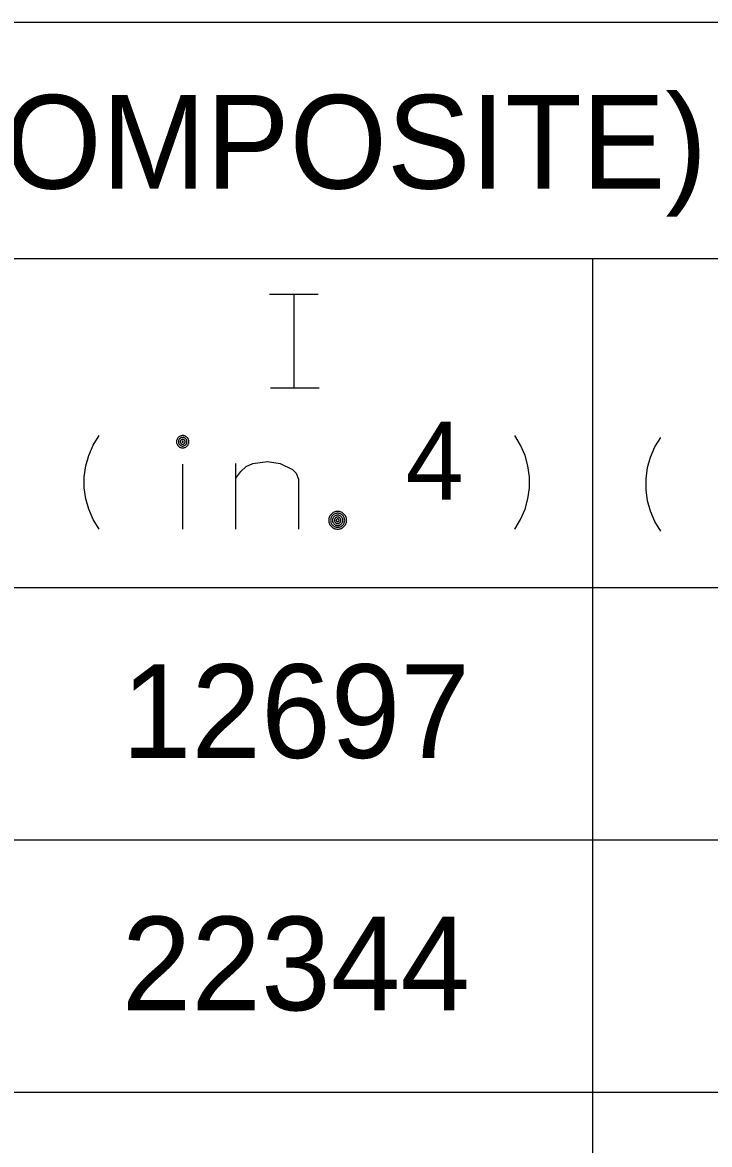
# Model space of a CAD drawing. Extents: x 635698 to 639877, y 296617 to 300175.
# Drawn here: x 639271.54 to 639293.54, y 299928.62 to 299964.57 of the extents above; entities that cross this region are included whole.
import ezdxf

# ---------------------------------------------------------------- set-up
doc = ezdxf.new("R2010")
doc.units = 0
doc.layers.add('1', color=7, linetype='Continuous')
doc.layers.add('3', color=7, linetype='Continuous')

msp = doc.modelspace()

# ---------------------------------------------------------------- linework, layer by layer
at = {"layer": '1'}
for p, q in [((639324.489, 299964.569), (639056.863, 299964.569)), ((639324.443, 299956.999), (639199.996, 299956.999)), ((639289.794, 299956.999), (639289.794, 299833.29)), ((639324.474, 299946.456), (639199.998, 299946.456)), ((639324.489, 299938.372), (639199.977, 299938.372)), ((639324.443, 299938.372), (639199.998, 299938.372)), ((639324.458, 299930.287), (639199.956, 299930.287)), ((639324.489, 299930.287), (639199.977, 299930.287))]:
    msp.add_line(p, q, dxfattribs=at)
at = {"layer": '3'}
for p, q in [((639279.457, 299955.864), (639281.01, 299955.864)), ((639279.486, 299952.859), (639281.039, 299952.859))]:
    msp.add_line(p, q, dxfattribs=at)
for points in [[(639279.885, 299955.862), (639280.593, 299955.862)], [(639280.239, 299952.862), (639280.239, 299955.862)], [(639279.885, 299952.862), (639280.593, 299952.862)], [(639273.995, 299948.335), (639273.806, 299948.642), (639273.664, 299948.973), (639273.57, 299949.303), (639273.522, 299949.658), (639273.522, 299950.012), (639273.57, 299950.367), (639273.664, 299950.697), (639273.806, 299951.028), (639273.995, 299951.335)], [(639276.871, 299951.137), (639276.87, 299951.157), (639276.867, 299951.178), (639276.861, 299951.198), (639276.854, 299951.217), (639276.844, 299951.236), (639276.833, 299951.253), (639276.82, 299951.269), (639276.805, 299951.284), (639276.789, 299951.297), (639276.772, 299951.308), (639276.754, 299951.318), (639276.734, 299951.325), (639276.714, 299951.33), (639276.694, 299951.334), (639276.673, 299951.335), (639276.652, 299951.334), (639276.632, 299951.33), (639276.612, 299951.325), (639276.592, 299951.318), (639276.574, 299951.308), (639276.557, 299951.297), (639276.54, 299951.284), (639276.526, 299951.269), (639276.513, 299951.253), (639276.502, 299951.236), (639276.492, 299951.217), (639276.485, 299951.198), (639276.479, 299951.178), (639276.476, 299951.157), (639276.475, 299951.137), (639276.476, 299951.116), (639276.479, 299951.095), (639276.485, 299951.076), (639276.492, 299951.056), (639276.502, 299951.038), (639276.513, 299951.02), (639276.526, 299951.004), (639276.54, 299950.99), (639276.557, 299950.976), (639276.574, 299950.965), (639276.592, 299950.956), (639276.612, 299950.949), (639276.632, 299950.943), (639276.652, 299950.94), (639276.673, 299950.939), (639276.694, 299950.94), (639276.714, 299950.943), (639276.734, 299950.949), (639276.754, 299950.956), (639276.772, 299950.965), (639276.789, 299950.977), (639276.805, 299950.99), (639276.82, 299951.004), (639276.833, 299951.02), (639276.844, 299951.038), (639276.854, 299951.056), (639276.861, 299951.076), (639276.867, 299951.095), (639276.87, 299951.116), (639276.871, 299951.137)], [(639287.304, 299948.335), (639287.493, 299948.642), (639287.634, 299948.973), (639287.729, 299949.303), (639287.776, 299949.658), (639287.776, 299950.012), (639287.729, 299950.367), (639287.634, 299950.697), (639287.493, 299951.028), (639287.304, 299951.335)], [(639276.811, 299951.137), (639276.81, 299951.151), (639276.808, 299951.165), (639276.804, 299951.179), (639276.799, 299951.193), (639276.792, 299951.206), (639276.785, 299951.218), (639276.776, 299951.229), (639276.765, 299951.239), (639276.754, 299951.248), (639276.742, 299951.256), (639276.729, 299951.263), (639276.715, 299951.268), (639276.702, 299951.272), (639276.687, 299951.274), (639276.673, 299951.275), (639276.658, 299951.274), (639276.644, 299951.272), (639276.63, 299951.268), (639276.617, 299951.263), (639276.604, 299951.256), (639276.592, 299951.248), (639276.581, 299951.239), (639276.57, 299951.229), (639276.561, 299951.218), (639276.553, 299951.206), (639276.547, 299951.193), (639276.542, 299951.179), (639276.538, 299951.165), (639276.536, 299951.151), (639276.535, 299951.137), (639276.536, 299951.122), (639276.538, 299951.108), (639276.542, 299951.094), (639276.547, 299951.081), (639276.553, 299951.068), (639276.561, 299951.055), (639276.57, 299951.044), (639276.581, 299951.034), (639276.592, 299951.025), (639276.604, 299951.017), (639276.617, 299951.011), (639276.63, 299951.006), (639276.644, 299951.002), (639276.658, 299950.999), (639276.673, 299950.999), (639276.687, 299950.999), (639276.702, 299951.002), (639276.715, 299951.006), (639276.729, 299951.011), (639276.742, 299951.017), (639276.754, 299951.025), (639276.765, 299951.034), (639276.776, 299951.044), (639276.785, 299951.055), (639276.792, 299951.068), (639276.799, 299951.081), (639276.804, 299951.094), (639276.808, 299951.108), (639276.81, 299951.122), (639276.811, 299951.137)], [(639276.751, 299951.137), (639276.751, 299951.145), (639276.749, 299951.153), (639276.747, 299951.161), (639276.744, 299951.168), (639276.74, 299951.176), (639276.736, 299951.183), (639276.731, 299951.189), (639276.725, 299951.195), (639276.719, 299951.2), (639276.712, 299951.204), (639276.705, 299951.208), (639276.697, 299951.211), (639276.689, 299951.213), (639276.681, 299951.214), (639276.673, 299951.215), (639276.665, 299951.214), (639276.657, 299951.213), (639276.649, 299951.211), (639276.641, 299951.208), (639276.634, 299951.204), (639276.627, 299951.2), (639276.621, 299951.195), (639276.615, 299951.189), (639276.61, 299951.183), (639276.605, 299951.176), (639276.602, 299951.168), (639276.599, 299951.161), (639276.596, 299951.153), (639276.595, 299951.145), (639276.595, 299951.137), (639276.595, 299951.129), (639276.596, 299951.121), (639276.599, 299951.113), (639276.602, 299951.105), (639276.605, 299951.098), (639276.61, 299951.091), (639276.615, 299951.084), (639276.621, 299951.079), (639276.627, 299951.074), (639276.634, 299951.069), (639276.641, 299951.065), (639276.649, 299951.062), (639276.657, 299951.061), (639276.665, 299951.059), (639276.673, 299951.059), (639276.681, 299951.059), (639276.689, 299951.061), (639276.697, 299951.062), (639276.705, 299951.065), (639276.712, 299951.069), (639276.719, 299951.074), (639276.725, 299951.079), (639276.731, 299951.084), (639276.736, 299951.091), (639276.74, 299951.098), (639276.744, 299951.105), (639276.747, 299951.113), (639276.749, 299951.121), (639276.751, 299951.129), (639276.751, 299951.137)], [(639276.691, 299951.137), (639276.691, 299951.139), (639276.691, 299951.14), (639276.69, 299951.142), (639276.689, 299951.144), (639276.688, 299951.146), (639276.687, 299951.147), (639276.686, 299951.149), (639276.685, 299951.15), (639276.684, 299951.151), (639276.682, 299951.152), (639276.68, 299951.153), (639276.678, 299951.154), (639276.677, 299951.154), (639276.675, 299951.155), (639276.673, 299951.155), (639276.671, 299951.155), (639276.669, 299951.154), (639276.668, 299951.154), (639276.666, 299951.153), (639276.664, 299951.152), (639276.662, 299951.151), (639276.661, 299951.15), (639276.659, 299951.149), (639276.658, 299951.147), (639276.657, 299951.146), (639276.657, 299951.144), (639276.656, 299951.142), (639276.655, 299951.14), (639276.655, 299951.139), (639276.655, 299951.137), (639276.655, 299951.135), (639276.655, 299951.133), (639276.656, 299951.131), (639276.657, 299951.129), (639276.657, 299951.128), (639276.658, 299951.126), (639276.659, 299951.125), (639276.661, 299951.123), (639276.662, 299951.122), (639276.664, 299951.121), (639276.666, 299951.12), (639276.668, 299951.12), (639276.669, 299951.119), (639276.671, 299951.119), (639276.673, 299951.119), (639276.675, 299951.119), (639276.677, 299951.119), (639276.678, 299951.12), (639276.68, 299951.12), (639276.682, 299951.121), (639276.684, 299951.122), (639276.685, 299951.123), (639276.686, 299951.125), (639276.687, 299951.126), (639276.688, 299951.128), (639276.689, 299951.129), (639276.69, 299951.131), (639276.691, 299951.133), (639276.691, 299951.135), (639276.691, 299951.137)], [(639291.985, 299948.276), (639291.796, 299948.583), (639291.654, 299948.914), (639291.559, 299949.244), (639291.512, 299949.599), (639291.512, 299949.953), (639291.559, 299950.308), (639291.654, 299950.638), (639291.796, 299950.969), (639291.985, 299951.276)], [(639276.673, 299948.335), (639276.673, 299950.413)], [(639278.374, 299949.965), (639278.539, 299950.178), (639278.705, 299950.343), (639278.918, 299950.437), (639279.39, 299950.508), (639279.791, 299950.437), (639280.193, 299950.248), (639280.311, 299950.13), (639280.382, 299949.941), (639280.382, 299948.335)], [(639278.374, 299948.335), (639278.374, 299950.437)], [(639281.92, 299948.62), (639281.919, 299948.649), (639281.914, 299948.679), (639281.907, 299948.708), (639281.896, 299948.736), (639281.882, 299948.762), (639281.866, 299948.787), (639281.847, 299948.81), (639281.826, 299948.831), (639281.803, 299948.85), (639281.778, 299948.867), (639281.751, 299948.88), (639281.723, 299948.891), (639281.695, 299948.898), (639281.665, 299948.903), (639281.636, 299948.905), (639281.606, 299948.903), (639281.576, 299948.898), (639281.547, 299948.891), (639281.519, 299948.88), (639281.493, 299948.867), (639281.468, 299948.85), (639281.445, 299948.831), (639281.423, 299948.81), (639281.405, 299948.787), (639281.389, 299948.762), (639281.375, 299948.736), (639281.365, 299948.708), (639281.357, 299948.679), (639281.352, 299948.649), (639281.351, 299948.62), (639281.352, 299948.59), (639281.357, 299948.56), (639281.365, 299948.532), (639281.375, 299948.504), (639281.389, 299948.477), (639281.405, 299948.452), (639281.423, 299948.429), (639281.445, 299948.408), (639281.468, 299948.389), (639281.493, 299948.373), (639281.519, 299948.359), (639281.547, 299948.349), (639281.576, 299948.341), (639281.606, 299948.336), (639281.636, 299948.335), (639281.665, 299948.336), (639281.695, 299948.341), (639281.723, 299948.349), (639281.751, 299948.359), (639281.778, 299948.373), (639281.803, 299948.389), (639281.826, 299948.408), (639281.847, 299948.429), (639281.866, 299948.452), (639281.882, 299948.477), (639281.896, 299948.504), (639281.907, 299948.532), (639281.914, 299948.56), (639281.919, 299948.59), (639281.92, 299948.62)], [(639281.86, 299948.62), (639281.859, 299948.643), (639281.856, 299948.666), (639281.849, 299948.689), (639281.841, 299948.711), (639281.83, 299948.732), (639281.818, 299948.752), (639281.803, 299948.77), (639281.786, 299948.787), (639281.768, 299948.802), (639281.748, 299948.815), (639281.727, 299948.825), (639281.705, 299948.834), (639281.682, 299948.84), (639281.659, 299948.844), (639281.636, 299948.845), (639281.612, 299948.844), (639281.589, 299948.84), (639281.566, 299948.834), (639281.544, 299948.825), (639281.523, 299948.815), (639281.503, 299948.802), (639281.485, 299948.787), (639281.468, 299948.77), (639281.454, 299948.752), (639281.441, 299948.732), (639281.43, 299948.711), (639281.421, 299948.689), (639281.415, 299948.666), (639281.412, 299948.643), (639281.41, 299948.62), (639281.412, 299948.596), (639281.415, 299948.573), (639281.421, 299948.55), (639281.43, 299948.528), (639281.441, 299948.507), (639281.454, 299948.488), (639281.468, 299948.469), (639281.485, 299948.452), (639281.503, 299948.438), (639281.523, 299948.425), (639281.544, 299948.414), (639281.566, 299948.406), (639281.589, 299948.4), (639281.612, 299948.396), (639281.636, 299948.395), (639281.659, 299948.396), (639281.682, 299948.4), (639281.705, 299948.406), (639281.727, 299948.414), (639281.748, 299948.425), (639281.768, 299948.438), (639281.786, 299948.452), (639281.803, 299948.469), (639281.818, 299948.488), (639281.83, 299948.507), (639281.841, 299948.528), (639281.849, 299948.55), (639281.856, 299948.573), (639281.859, 299948.596), (639281.86, 299948.62)], [(639281.8, 299948.62), (639281.8, 299948.637), (639281.797, 299948.654), (639281.792, 299948.671), (639281.786, 299948.687), (639281.778, 299948.702), (639281.769, 299948.717), (639281.758, 299948.73), (639281.746, 299948.742), (639281.733, 299948.753), (639281.718, 299948.763), (639281.703, 299948.77), (639281.686, 299948.777), (639281.67, 299948.781), (639281.653, 299948.784), (639281.636, 299948.785), (639281.618, 299948.784), (639281.601, 299948.781), (639281.585, 299948.777), (639281.568, 299948.77), (639281.553, 299948.763), (639281.538, 299948.753), (639281.525, 299948.742), (639281.513, 299948.73), (639281.502, 299948.717), (639281.493, 299948.702), (639281.485, 299948.687), (639281.478, 299948.671), (639281.474, 299948.654), (639281.471, 299948.637), (639281.47, 299948.62), (639281.471, 299948.603), (639281.474, 299948.585), (639281.478, 299948.569), (639281.485, 299948.552), (639281.493, 299948.537), (639281.502, 299948.523), (639281.513, 299948.509), (639281.525, 299948.497), (639281.538, 299948.486), (639281.553, 299948.477), (639281.568, 299948.469), (639281.585, 299948.463), (639281.601, 299948.458), (639281.618, 299948.456), (639281.636, 299948.455), (639281.653, 299948.456), (639281.67, 299948.458), (639281.686, 299948.463), (639281.703, 299948.469), (639281.718, 299948.477), (639281.733, 299948.486), (639281.746, 299948.497), (639281.758, 299948.509), (639281.769, 299948.523), (639281.778, 299948.537), (639281.786, 299948.552), (639281.792, 299948.569), (639281.797, 299948.585), (639281.8, 299948.603), (639281.8, 299948.62)], [(639281.74, 299948.62), (639281.74, 299948.631), (639281.738, 299948.641), (639281.735, 299948.652), (639281.731, 299948.662), (639281.726, 299948.672), (639281.72, 299948.681), (639281.714, 299948.69), (639281.706, 299948.698), (639281.697, 299948.705), (639281.688, 299948.711), (639281.678, 299948.716), (639281.668, 299948.719), (639281.657, 299948.722), (639281.647, 299948.724), (639281.636, 299948.725), (639281.625, 299948.724), (639281.614, 299948.722), (639281.603, 299948.719), (639281.593, 299948.716), (639281.583, 299948.711), (639281.574, 299948.705), (639281.565, 299948.698), (639281.558, 299948.69), (639281.551, 299948.681), (639281.544, 299948.672), (639281.54, 299948.662), (639281.536, 299948.652), (639281.533, 299948.641), (639281.531, 299948.631), (639281.53, 299948.62), (639281.531, 299948.609), (639281.533, 299948.598), (639281.536, 299948.587), (639281.54, 299948.577), (639281.544, 299948.567), (639281.551, 299948.558), (639281.558, 299948.549), (639281.565, 299948.542), (639281.574, 299948.535), (639281.583, 299948.529), (639281.593, 299948.524), (639281.603, 299948.52), (639281.614, 299948.517), (639281.625, 299948.515), (639281.636, 299948.515), (639281.647, 299948.515), (639281.657, 299948.517), (639281.668, 299948.52), (639281.678, 299948.524), (639281.688, 299948.529), (639281.697, 299948.535), (639281.706, 299948.542), (639281.714, 299948.549), (639281.72, 299948.558), (639281.726, 299948.567), (639281.731, 299948.577), (639281.735, 299948.587), (639281.738, 299948.598), (639281.74, 299948.609), (639281.74, 299948.62)], [(639281.681, 299948.62), (639281.68, 299948.625), (639281.679, 299948.629), (639281.678, 299948.634), (639281.677, 299948.638), (639281.674, 299948.642), (639281.672, 299948.646), (639281.669, 299948.65), (639281.666, 299948.653), (639281.662, 299948.656), (639281.658, 299948.659), (639281.654, 299948.661), (639281.649, 299948.663), (639281.645, 299948.664), (639281.64, 299948.664), (639281.636, 299948.665), (639281.631, 299948.664), (639281.626, 299948.664), (639281.622, 299948.663), (639281.617, 299948.661), (639281.613, 299948.659), (639281.609, 299948.656), (639281.606, 299948.653), (639281.602, 299948.65), (639281.599, 299948.646), (639281.596, 299948.642), (639281.594, 299948.638), (639281.593, 299948.634), (639281.592, 299948.629), (639281.591, 299948.625), (639281.59, 299948.62), (639281.591, 299948.615), (639281.592, 299948.61), (639281.593, 299948.606), (639281.594, 299948.601), (639281.596, 299948.597), (639281.599, 299948.593), (639281.602, 299948.59), (639281.606, 299948.586), (639281.609, 299948.583), (639281.613, 299948.581), (639281.617, 299948.578), (639281.622, 299948.577), (639281.626, 299948.576), (639281.631, 299948.575), (639281.636, 299948.575), (639281.64, 299948.575), (639281.645, 299948.576), (639281.649, 299948.577), (639281.654, 299948.578), (639281.658, 299948.581), (639281.662, 299948.583), (639281.666, 299948.586), (639281.669, 299948.59), (639281.672, 299948.593), (639281.674, 299948.597), (639281.677, 299948.601), (639281.678, 299948.606), (639281.679, 299948.61), (639281.68, 299948.615), (639281.681, 299948.62)]]:
    msp.add_lwpolyline(points, dxfattribs=at)

# ---------------------------------------------------------------- texts
at = {"layer": '1'}
for s, p in [('12697', (639274.72, 299941.007)), ('22344', (639274.72, 299932.924))]:
    msp.add_text(s, height=3, dxfattribs=at).set_placement(p)
at = {"layer": '3'}
for s, height, p in [('BASIC BEAM DATA - 36" BEAMS (COMPOSITE)', 2.99895, (639204.689, 299959.246)), ('4', 2.5, (639283.811, 299949.276))]:
    msp.add_text(s, height=height, dxfattribs=at).set_placement(p)

doc.saveas('drawing.dxf')
